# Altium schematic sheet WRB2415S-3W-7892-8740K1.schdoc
size 277 x 190 mm; Device: default297x210; Symbol: default297x210; Name: default297x210; Date: 2026/2/5; Size: "A4"; Id: /; Sheet: /; @Page No: 1; @Page Count: 1; @Schematic Name: URB2405S-3W-7892-8768K_V1.1; @Project Name: URB2405S-3W-7892-8768K; @Board Name: URB2405S-3W-7892-8768K_V1.1; @Update Date: 2025-09-23; @Create Time: 14:24:13; @Update Time: 15:26:56; @Page Name: URB2405S-3W-7892-8768K_V1.1; @Create Date: 2025-09-23; File: WRB2415S-3W-7892-8740K1
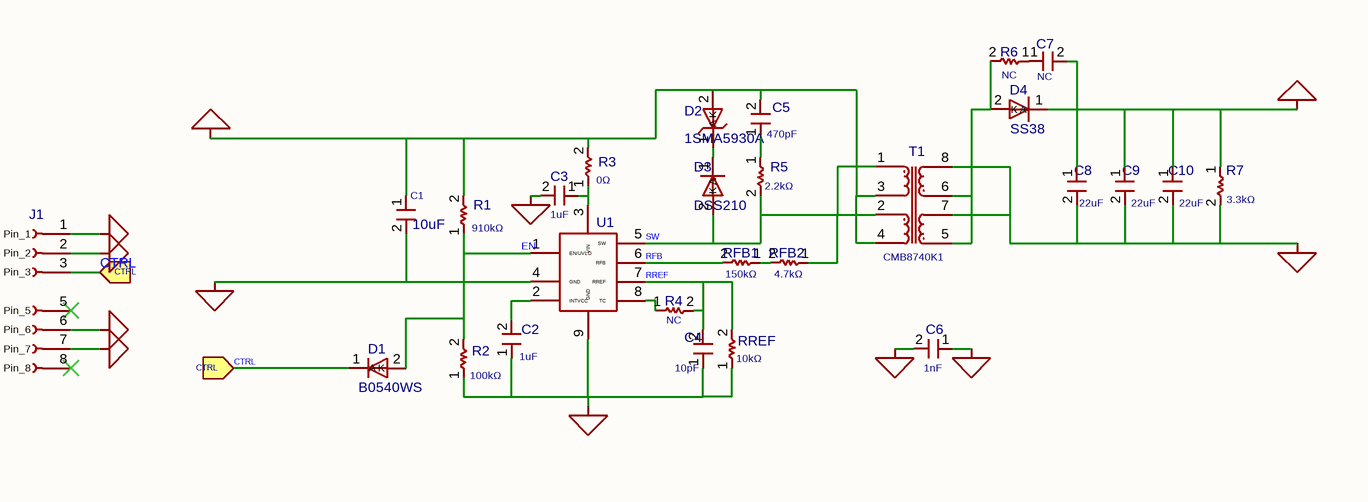
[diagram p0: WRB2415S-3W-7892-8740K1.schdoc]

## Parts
C1  10uF  [coileasy:C_1206]
C2  1uF  [coileasy:C_0603]
C3  1uF  [coileasy:C_0603]
C4  10pF  [coileasy:C_0603]
C5  470pF  [coileasy:C_0603]
C6  1nF  [coileasy:C_1206]
C7  value NC  [coileasy:C_0603]  (hidden comment: C)
C8  22uF  [coileasy:C_1206]
C9  22uF  [coileasy:C_1206]
C10  22uF  [coileasy:C_1206]
D1  B0540WS  [coileasy:SOD-323]
D2  1SMA5930A  [coileasy:SMA]
D3  DSS210  [coileasy:SOD-123FL]
D4  SS38  [coileasy:SMA]
J1  Coileasy_Conn_01x07_1  [coileasy:PinHeader_01x07_1_P2.54mm_Vertical]  (value not drawn)
R1  910kΩ  [coileasy:R_0603]
R2  100kΩ  [coileasy:R_0603]
R3  0Ω  [coileasy:R_0603]
R4  value NC  [coileasy:R_0603]  (hidden comment: R)
R5  2.2kΩ  [coileasy:R_0805]
R6  value NC  [coileasy:R_0603]  (hidden comment: R)
R7  3.3kΩ  [coileasy:R_0805]
RFB1  150kΩ  [coileasy:R_0603]
RFB2  4.7kΩ  [coileasy:R_0603]
RREF  10kΩ  [coileasy:R_0603]
T1  value CMB8740K1  [coileasy:SMD-8P, 11.55x9.6, ER9.5 4+4]  (hidden comment: MYLibrary _CMT_3+3)
U1  CMP7892  [coileasy:ESOP-8]  (value not drawn)

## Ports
CTRL (in)

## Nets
GND1: C1.2 C2.1 C3.2 C4.1 C6.2 J1.1(Pin_1) R2.1 RREF.1 U1.4(GND) U1.9(GND)
GND2: C6.1 C8.2 C9.2 C10.2 J1.7(Pin_7) R7.2 T1.7 T1.8
VIN: C1.1 C5.2 D2.2(A) J1.2(Pin_2) R1.2 R3.2 T1.3 T1.4
VOUT: C7.2 C8.1 C9.1 C10.1 D4.1(K) J1.6(Pin_6) R7.1
CTRL: D1.1(K) J1.3(Pin_3) ; port CTRL
EN: D1.2(A) R1.1 R2.2 U1.1(EN/UVLO)
RFB: RFB1.2 U1.6(RFB)
RREF: C4.2 R4.2 RREF.2 U1.7(RREF)
SW: D3.2(A) R5.2 RFB2.1 T1.1 T1.2 U1.5(SW)
NetC2_2: C2.2 U1.2(INTVCC)
NetC3_1: C3.1 R3.1 U1.3(VIN)
NetC5_1: C5.1 R5.1
NetC7_1: C7.1 R6.1
NetD2_1: D2.1(K) D3.1(K)
NetD4_2: D4.2(A) R6.2 T1.5 T1.6
NetR4_1: R4.1 U1.8(TC)
NetRFB1_1: RFB1.1 RFB2.2

Not connected (* = marked no-connect by the designer): J1 5(Pin_5)* 8(Pin_8)*

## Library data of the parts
C1 = CL31A106KBHNNNE: 容值:10uF;精度:±10%;额定电压:50V;温度系数:X5R;; Manufacturer: SAMSUNG(三星); Add into BOM: yes; 3D Model: e4be705b945545a48e666415e3682bd8; 3D Model Transform: 125.984,62.992,0,0,0,0,0,0,0; Tolerance: ±10%; Voltage Rating: 50V; Temperature Coefficient: X5R; Symbol: C; ModelName: C1206_L3.2-W1.6-H1.3
C2 C3 = 0603X105K500NT: 容值:1uF;精度:±10%;额定电压:50V;温度系数:X5R;; Manufacturer: FH(风华); Add into BOM: yes; Symbol: C; 3D Model: ac125912035d415993ca9572d50418b1; 3D Model Transform: 62.992,31.496,0,0,0,0,0,0,0; Tolerance: ±10%; Voltage Rating: 50V; Temperature Coefficient: X5R; ModelName: C0603_L1.6-W0.8-H0.8
C4 = CC0603JRNPO9BN100: 容值:10pF;精度:±5%;额定电压:50V;温度系数:NP0;; Manufacturer: YAGEO(国巨); Add into BOM: yes; 3D Model: ac125912035d415993ca9572d50418b1; 3D Model Transform: 62.992,31.496,0,0,0,0,0,0,0; Tolerance: ±5%; Voltage Rating: 50V; Temperature Coefficient: NP0; Symbol: C; ModelName: C0603_L1.6-W0.8-H0.8
C5 = CC0603KRX7R9BB471: 容值:470pF;精度:±10%;额定电压:50V;材质(温度系数):X7R;; Manufacturer: YAGEO(国巨); Add into BOM: yes; Symbol: C; 3D Model: ac125912035d415993ca9572d50418b1; 3D Model Transform: 62.992,31.496,0,0,0,0,0,0,0; Tolerance: ±10%; Voltage Rated: 50V; Temperature Coefficient: X7R; ModelName: C0603_L1.6-W0.8-H0.8
C6 = CC1206KKX7RDBB102: 容值:1nF;精度:±10%;额定电压:2kV;温度系数:X7R;; Manufacturer: YAGEO(国巨); Add into BOM: yes; Symbol: C; 3D Model: e4be705b945545a48e666415e3682bd8; 3D Model Transform: 125.984,62.992,0,0,0,0,0,0,0; Tolerance: ±10%; Temperature Coefficient: X7R; Voltage Rating: 2kV; ModelName: C1206_L3.2-W1.6-H1.3
C7 = C: Add into BOM: yes
C8 = CL31A226KAHNNNE: 容值:22uF;精度:±10%;额定电压:25V;温度系数:X5R;; Manufacturer: SAMSUNG(三星); Add into BOM: yes; Symbol: C; 3D Model: e4be705b945545a48e666415e3682bd8; 3D Model Transform: 125.984,62.992,0,0,0,0,0,0,0; Tolerance: ±10%; Voltage Rating: 25V; Temperature Coefficient: X5R; ModelName: C1206_L3.2-W1.6-H1.3
C9 C10 = CL31A226KAHNNNE: 容值:22uF;精度:±10%;额定电压:25V;温度系数:X5R;; Manufacturer: SAMSUNG(三星); Add into BOM: yes; 3D Model: e4be705b945545a48e666415e3682bd8; 3D Model Transform: 125.984,62.992,0,0,0,0,0,0,0; Temperature Coefficient: X5R; Symbol: C; Tolerance: ±10%; Voltage Rating: 25V; ModelName: C1206_L3.2-W1.6-H1.3
D1 = B0540WS_C475613: 二极管配置:独立式;正向压降(Vf):600mV@200mA;直流反向耐压(Vr):40V;整流电流:350mA;; Manufacturer: SHIKUES(时科); Add into BOM: yes; 3D Model: 7459fe65e23146c0a8d836e46a0add72; 3D Model Transform: 104.3305,51.181,0,0,0,0,0,0,0; Diode Configuration: 独立式; Voltage - DC Reverse(Vr): 40V; Current - Rectified: 350mA; Reverse Leakage Current (Ir): 5uA@30V; Non-Repetitive Peak Forward Surge Current: 1.5A; Symbol: Coileasy library_D; ModelName: SOD-323_L1.8-W1.3-LS2.5-RD
D2 = 1SMA5930A: 二极管配置:独立式;稳压值(标称值):16V;稳压值(范围):14.4V~17.6V;耗散功率(Pd):1.5W;; Manufacturer: LGE(鲁光); Add into BOM: yes; 3D Model: e3551acb3c5a4975a5e9d36087fe1fa2; 3D Model Transform: 185.039,102.362,0,0,0,0,0,0,0; Diode Configuration: 独立式; Zener Voltage(Nom): 16V; Reverse Leakage Current (Ir): 1uA@12.2V; Pd - Power Dissipation: 1.5W; Impedance(Zzt): 10Ω; Impedance(Zzk): 600Ω; Operating Junction Temperature Range: -55℃~+150℃; Symbol: My library_D_Zener; ModelName: SMA_L4.3-W2.6-LS5.2-RD
D3 = DSS210: 二极管配置:独立式;正向压降(Vf):850mV@2A;直流反向耐压(Vr):100V;整流电流:2A;; Manufacturer: CJ(江苏长电/长晶); Add into BOM: yes; Symbol: My library_DSS210; 3D Model: 125b22121bda4d3999c0a2016797619b; 3D Model Transform: 145.669,70.866,0,0,0,0,0,0,0; Diode Configuration: 独立式; Voltage - DC Reverse(Vr): 100V; Current - Rectified: 2A; Reverse Leakage Current (Ir): 100uA@100V; Operating Junction Temperature Range: -55℃~+150℃; Non-Repetitive Peak Forward Surge Current: 40A; ModelName: SOD-123_L2.8-W1.8-H1.4-LS3.7
D4 = SS38_C64999: 二极管配置:独立式;正向压降(Vf):700mV@3A;直流反向耐压(Vr):80V;整流电流:3A;; Manufacturer: MDD(辰达半导体); Add into BOM: yes; 3D Model: 4caf566195a049cf809ac17c4d641932; Symbol: My library_DSS210; 3D Model Transform: 204.724,102.362,0,0,0,0,0,0,0; Voltage - DC Reverse(Vr): 80V; Current - Rectified: 3A; Reverse Leakage Current (Ir): 500uA@80V; Operating Junction Temperature Range: -55℃~+125℃; Diode Configuration: 独立式; ModelName: SMA_L4.4-W2.8-LS5.4-RD
J1 = Coileasy_Conn_01x07_1: Value: Conn_01x08-1; ki_fp_filters: Connector*:*_1x??_*; AddInBom: yes
R1 = RC0603FR-07910KL: 电阻类型:厚膜电阻;阻值:910kΩ;精度:±1%;功率:100mW;工作电压:75V;温度系数:±100ppm/℃;; Manufacturer: YAGEO(国巨); Add into BOM: yes; 3D Model: fc143cca1e79419f9cd78b61e9279f08; 3D Model Transform: 31.8897,63.7794,0,90,0,0,0,0,0; Tolerance: ±1%; Power(Watts): 100mW; Symbol: R; Voltage-Supply(Max): 75V; ModelName: R0603
R2 = RC0603FR-07100KL: 电阻类型:厚膜电阻;阻值:100kΩ;精度:±1%;功率:100mW;最大工作电压:75V;温度系数:±100ppm/℃;; Manufacturer: YAGEO(国巨); Add into BOM: yes; Symbol: R; 3D Model: fc143cca1e79419f9cd78b61e9279f08; 3D Model Transform: 31.8897,63.7794,0,90,0,0,0,0,0; Tolerance: ±1%; Power(Watts): 100mW; Overload Voltage (Max): 75V; ModelName: R0603
R3 = RC0603FR-070RL: 电阻类型:厚膜电阻;阻值:0Ω;精度:±1%;功率:100mW;工作电压:75V;温度系数:-;; Manufacturer: YAGEO(国巨); Add into BOM: yes; Symbol: R; 3D Model: fc143cca1e79419f9cd78b61e9279f08; 3D Model Transform: 31.8897,63.7794,0,90,0,0,0,0,0; Tolerance: ±1%; Power(Watts): 100mW; Voltage-Supply(Max): 75V; ModelName: R0603
R4 R6 = R: Resistor; ki_fp_filters: R_*; AddInBom: yes
R5 = RC0805FR-072K2L: 电阻类型:厚膜电阻;阻值:2.2kΩ;精度:±1%;功率:125mW;工作电压:150V;温度系数:±100ppm/℃;; Manufacturer: YAGEO(国巨); Add into BOM: yes; 3D Model: 37a81e68749a4138bd2dfa6897b24b85; 3D Model Transform: 78.74,51.181,0,0,0,0,0,-0.0005,0; Tolerance: ±1%; Power(Watts): 125mW; Voltage-Supply(Max): 150V; Symbol: R; ModelName: R0805_L2.0-W1.3-H0.6
R7 = RC0805FR-073K3L: 电阻类型:厚膜电阻;阻值:3.3kΩ;精度:±1%;功率:125mW;工作电压:150V;温度系数:±100ppm/℃;; Manufacturer: YAGEO(国巨); Add into BOM: yes; 3D Model: 37a81e68749a4138bd2dfa6897b24b85; 3D Model Transform: 78.74,51.181,0,0,0,0,0,-0.0005,0; Tolerance: ±1%; Power(Watts): 125mW; Voltage-Supply(Max): 150V; Symbol: R; ModelName: R0805_L2.0-W1.3-H0.6
RFB1 = RC0603FR-07150KL: 电阻类型:厚膜电阻;阻值:150kΩ;精度:±1%;功率:100mW;最大工作电压:75V;温度系数:±100ppm/℃;; Manufacturer: YAGEO(国巨); Add into BOM: yes; 3D Model: fc143cca1e79419f9cd78b61e9279f08; 3D Model Transform: 31.8897,63.7794,0,90,0,0,0,0,0; Tolerance: ±1%; Power(Watts): 100mW; Symbol: R; Overload Voltage (Max): 75V; ModelName: R0603
RFB2 = RC0603FR-074K7L: 电阻类型:厚膜电阻;阻值:4.7kΩ;精度:±1%;功率:100mW;工作电压:75V;温度系数:±100ppm/℃;; Manufacturer: YAGEO(国巨); Add into BOM: yes; 3D Model: fc143cca1e79419f9cd78b61e9279f08; 3D Model Transform: 31.8897,63.7794,0,90,0,0,0,0,0; Tolerance: ±1%; Power(Watts): 100mW; Voltage-Supply(Max): 75V; Symbol: R; ModelName: R0603
RREF = RC0603FR-0710KL: 电阻类型:厚膜电阻;阻值:10kΩ;精度:±1%;功率:100mW;最大工作电压:75V;温度系数:±100ppm/℃;; Manufacturer: YAGEO(国巨); Add into BOM: yes; 3D Model: fc143cca1e79419f9cd78b61e9279f08; 3D Model Transform: 31.8897,63.7794,0,90,0,0,0,0,0; Tolerance: ±1%; Power(Watts): 100mW; Overload Voltage (Max): 75V; Symbol: R; ModelName: R0603
T1 = MYLibrary _CMT_3+3: Symbol: CMT_3+3_1; AddInBom: yes
U1 = CMP7892: Manufacturer: coileasy(线易); Add into BOM: yes; 3D Model: f43fc10339aa42ce991094e4756959b9; 3D Model Transform: 192.913,236.22,0,0,0,0,0,0,0; Symbol: Coileasy_CMP7892; ModelName: ESOP-8_L4.9-W3.9-P1.27-LS6.0-BL-EP3.3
